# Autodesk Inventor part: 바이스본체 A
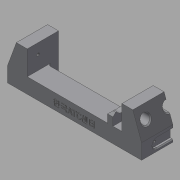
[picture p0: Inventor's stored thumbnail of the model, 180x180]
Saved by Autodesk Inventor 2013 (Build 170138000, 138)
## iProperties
Created: 2017-04
Part Number: 바이스본체 A
Material: 알루미늄 6061
Document SubType Name: Modeling
Designer: mduedu
Density: 1 g/cm^3
Author: mduedu
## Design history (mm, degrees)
sketch "스케치1"
  geometry: L1 (-75, 0)-(75, 0); L2 (-75, 0)-(-75, 17); L3 (-53, 17)-(53, 17); L4 (75, 17)-(75, 0); L5 (-75, 17)-(-65.173, 44); L6 (-65.173, 44)-(-53, 44); L7 (-53, 44)-(-53, 17); L8 (0, 0)-(0, 17); L9 (75, 17)-(65.173, 44); L10 (65.173, 44)-(53, 44); L11 (53, 44)-(53, 17); 1 further point
  constraints: 22 end point, 4 perpendicular, 2 horizontal alignment, 2 midpoint, 2 symmetric about line, 1 coincident, 1 collinear, 1 horizontal, 1 vertical
  dimensions: "d0" = 150 distance of L1.start L1.end; "d1" = 17 distance of L1.start L2.end; "d2" = 27 distance of L3.start L6.end; "d3" = 22 distance of L3.start L2.end; "d4" = 70 deg angle of L3 L5; "d54" = 20 deg angle of L9 L4
extrude "돌출1" new body sketch "스케치1" stored distance "d5" = 70; taper "d6" = 0 deg
sketch "스케치2"
  geometry: L1 (0, 70)-(106, 70) reference; L2 (106, 70)-(106, 0) reference; L3 (106, 0)-(0, 0) reference; L4 (0, 47)-(106, 47); L5 (106, 47)-(106, 23); L6 (106, 23)-(0, 23); L7 (0, 23)-(0, 47); L8 (0, 70)-(0, 0) reference; 2 further points
  constraints: 8 end point, 2 parallel, 2 point on line, 1 horizontal, 1 horizontal alignment, 1 midpoint, 1 perpendicular
  dimensions: "d7" = 24 distance between parallel lines of L6 L4
extrude "돌출2" cut sketch "스케치2" stored distance "d9" = 70; taper "d10" = 0 deg
sketch "스케치3"
  geometry: L1 (22, -23)-(128, -23) reference; L2 (128, -47)-(22, -47) reference; L3 (22, -18)-(128, -18); L4 (128, -52)-(22, -52); L5 (22, -18)-(22, -52); L6 (128, -18)-(128, -52); 1 further point
  constraints: 8 end point, 3 parallel, 2 point on line, 1 perpendicular
  dimensions: "d11" = 5 distance between parallel lines of L3 L1; "d12" = 5 distance between parallel lines of L4 L2
extrude "돌출3" cut sketch "스케치3" distance "d13" = 12; taper "d14" = 0 deg
fillet "모깎기1" dims "d15" = 3, "d16" = 3
sketch "스케치4"
  geometry: L1 (103, 23)-(3, 23) reference; L2 (0, 26)-(0, 0) reference; L3 (106, 0)-(0, 0) reference; L4 (106, 26)-(106, 0) reference; L5 (96, 0)-(90, 0); L6 (90, 0)-(90, 19.5); L7 (96, 19.5)-(96, 0); L8 (90, 19.5)-(96, 19.5); A1 r 3 centre (3, 26) between (0, 26) and (3, 23) reference; A2 r 3 centre (103, 26) between (103, 23) and (106, 26) reference; 1 further point
  constraints: 8 end point, 2 perpendicular, 1 horizontal, 1 parallel, 1 point on line
  dimensions: "d17" = 10 distance between parallel lines of L7 L4; "d18" = 6 distance between parallel lines of L7 L6; "d27" = 3.5 distance between parallel lines of L8 L1
extrude "돌출4" join sketch "스케치4" distance "d19" = 12; taper "d20" = 0 deg
chamfer "모따기1" distance "d21" = 3; stored, may be unused: second distance "d22" = 2, angle "d23" = 45 deg
chamfer "모따기2" distance "d24" = 3; stored, may be unused: second distance "d25" = 2, angle "d26" = 45 deg
sketch "스케치5"
  geometry: L1 (-15.5, 35.8)-(-15.5, -25.8) reference; L2 (19.5, 0)-(0, 0) reference; C1 r 6.5 at (9.5, 15); 1 further point
  constraints: 1 centre point
  dimensions: "d28" = 13 diameter of C1; "d30" = 15 distance from line of C1.centre L2; "d31" = 25 distance from line of C1.centre L1
extrude "돌출5" cut sketch "스케치5" stored distance "d32" = 12; taper "d33" = 0 deg
sketch "스케치6"
  geometry: C1 r 5 at (-10, 15); C2 r 5 at (-60, 15); A1 r 6.5 centre (-10, 15) between (-15.766, 12) and (-4.234, 12) reference; A2 r 6.5 centre (-60, 15) between (-65.766, 12) and (-54.234, 12) reference; 1 further point
  constraints: 2 centre point, 2 coincident
  dimensions: "d34" = 10 diameter of C1; "d35" = 10 diameter of C2 (= d34)
extrude "돌출6" cut sketch "스케치6" stored distance "d36" = 12; taper "d37" = 0 deg
chamfer "모따기3" distance "d38" = 1; stored, may be unused: second distance "d39" = 2, angle "d40" = 45 deg
chamfer "모따기4" distance "d41" = 1; stored, may be unused: second distance "d42" = 2, angle "d43" = 45 deg
sketch "스케치7"
  geometry: L1 (-35, 35.8)-(-35, -25.8) reference; L2 (-70, 0)-(0, 0) reference; C1 r 5 at (-35, 15); 1 further point
  constraints: 1 centre point, 1 point on line
  dimensions: "d44" = 10 diameter of C1; "d45" = 15 distance from line of C1.centre L2
extrude "돌출7" cut sketch "스케치7" stored distance "d46" = 12; taper "d47" = 0 deg
chamfer "모따기5" distance "d48" = 1; stored, may be unused: second distance "d49" = 2, angle "d50" = 45 deg
node "작업축1"
sketch "스케치8"
  geometry: L1 (-105, 32)-(105, 32) reference; L2 (58, 32)-(64, 32); L3 (64, 32)-(64, 40); L4 (64, 40)-(58, 40); L5 (58, 40)-(58, 32); L6 (53, 38)-(53, 26) reference; 1 further point
  constraints: 8 end point, 2 parallel, 1 horizontal, 1 perpendicular, 1 point on line
  dimensions: "d51" = 5 distance from line of L6 L2.start; "d52" = 6 distance of L3.end L4.end; "d53" = 16 diameter of L4 L1
revolve "회전1" sketch "스케치8" stored, may be unused: angle "d55" = 90 deg
fillet "모깎기2"
chamfer "모따기6" distance "d56" = 1; stored, may be unused: second distance "d57" = 2, angle "d58" = 45 deg
sketch "스케치9"
  geometry: L1 (17.5, 3)-(52.5, 3); L2 (52.5, 13)-(17.5, 13); L3 (70, 0)-(0, 0) reference; L4 (17.5, 8)-(52.5, 8); A1 r 5 centre (17.5, 8) between (17.5, 13) and (17.5, 3); A2 r 5 centre (52.5, 8) between (52.5, 3) and (52.5, 13); 3 further points
  constraints: 6 end point, 4 point on circle, 3 tangent, 2 centre point, 2 midpoint, 2 parallel, 1 horizontal, 1 vertical alignment
  dimensions: "d59" = 35 distance of L4.start L4.end; "d61" = 5 radius of A2; "d62" = 8 distance between parallel lines of L3 L4
extrude "돌출8" cut sketch "스케치9" distance "d63" = 3; taper "d64" = 0 deg
chamfer "모따기7" distance "d65" = 1; stored, may be unused: second distance "d66" = 2, angle "d67" = 45 deg
chamfer "모따기8" distance "d68" = 1; stored, may be unused: second distance "d69" = 2, angle "d70" = 45 deg
feature "분할1"
sketch "스케치10"
  geometry: L1 (35, 27)-(0, 27) reference; L2 (0, 0)-(0, 27) reference; 1 further point
  dimensions: "d85" = 11.5 distance from line of point (12, 15.5) L1; "d86" = 12 distance from line of point (12, 15.5) L2
hole "구멍1" sketch "스케치10" at (12, 15.5) diameter "d71" = 3.242; stored, may be unused: countersink angle "d75" = 90 deg, drill point angle "d77" = 120 deg; dims "d72" = 6, "d73" = 4, "d74" = 2, "d76" = 8
sketch "스케치11"
  geometry: A1 r 5 centre (17.5, 8) between (17.5, 13) and (17.5, 3) reference; 1 further point
  constraints: 1 coincident
hole "구멍3" sketch "스케치11" at (17.5, 8) diameter "d78" = 2.459; stored, may be unused: countersink angle "d82" = 90 deg, drill point angle "d84" = 120 deg; dims "d79" = 4.5, "d80" = 4, "d81" = 2, "d83" = 6
sketch "스케치12"
  geometry: L1 (-75, 0)-(75, 0) reference; 3 further points
  constraints: 1 midpoint, 1 vertical alignment, 1 other
  dimensions: "d87" = 8 distance of point (0, 8) point (0, 0)
feature "엠보싱1" sketch "스케치12" dims "d7" = 24, "d88" = 0.5, "d89" = 0
node "솔리드1"
mirror "대칭1"
mirror "대칭2"
mirror "대칭3"
mirror "대칭4"
node "투영된 루프1"
